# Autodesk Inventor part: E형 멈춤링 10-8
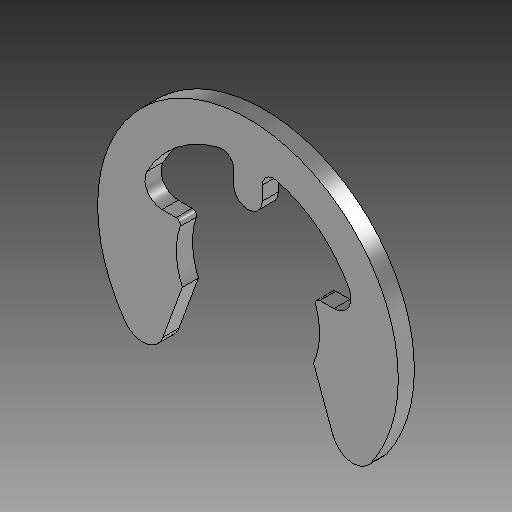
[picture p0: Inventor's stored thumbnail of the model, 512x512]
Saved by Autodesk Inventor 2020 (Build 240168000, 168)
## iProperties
Created: 2024-08
Part Number: E형 멈춤링 10-8
Material: 강철, 연강
Description: 일반용 테이퍼 및 줄어든 횡단면 리테이닝 링 - E-링 외부 시리즈 3CM1 리테이닝 링
Document SubType Name: Modeling
Designer: 1강의실14
Density: 7.85 g/cm^3
Appearance: 기본값
Author: jhkim
Sending System: Autodesk Inventor 2025
Preprocessor: ST-DEVELOPER v20
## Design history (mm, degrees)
feature "Solid1"
node "솔리드1"
